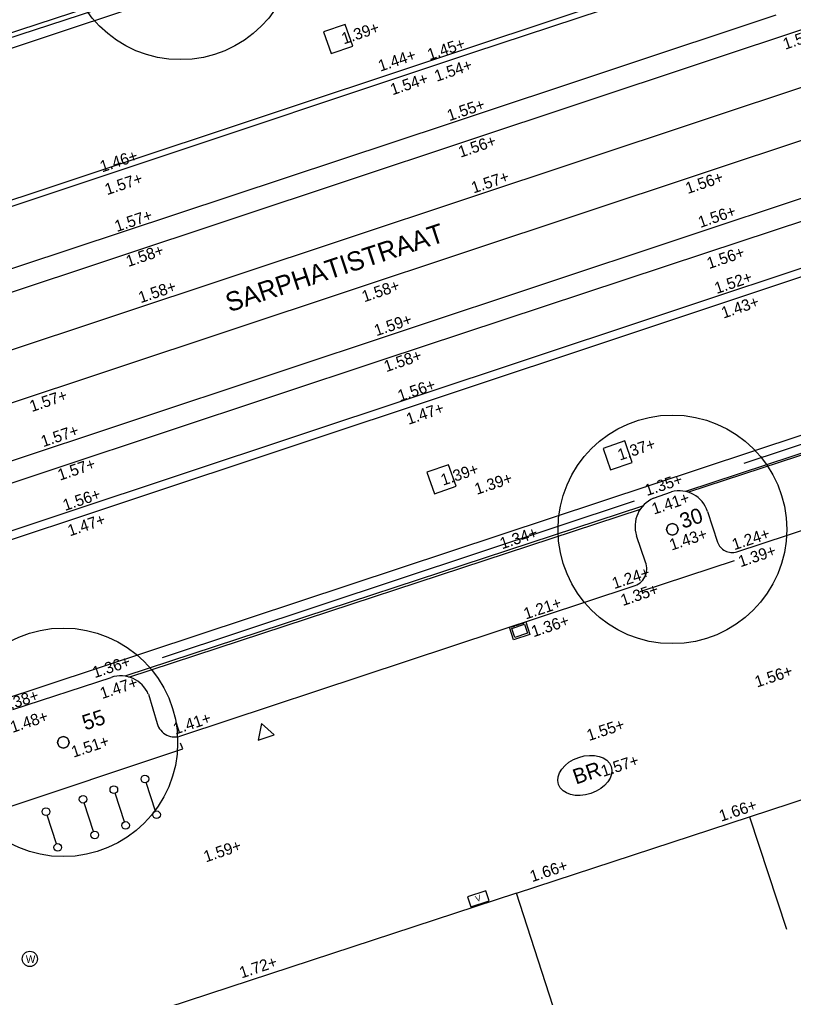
# Model space of a CAD drawing. Extents: x 122462 to 123306, y 485548 to 486417.
# Drawn here: x 122686.41 to 122706.71, y 486120.56 to 486146.23 of the extents above; entities that cross this region are included whole.
import ezdxf

# ---------------------------------------------------------------- set-up
doc = ezdxf.new("R2010")
doc.units = 0
for name, color, linetype in [('B meubilair trammast', 7, 'Continuous'), ('B RWS-band 115-225x250 mm specie', 7, 'Continuous'), ('B-WE-GR-BOOM-S', 7, 'Continuous'), ('B-WE-GR-BOOM_BOOMDIAMETER', 7, 'Continuous'), ('B-WE-IE-MEUBILAIR_WEGMEUBILAIR-S', 7, 'Continuous'), ('B-WE-IE-MEUBILAIR_WEGMEUBILAIR_FIETSNIETJE-S', 7, 'Continuous'), ('B-WE-KL-DATA_TELECOM_KAST-S', 7, 'Continuous'), ('B-WE-OG-HOOGTEPUNT-S', 7, 'Continuous'), ('B-WE-OG-TOPOGRAFIE_RAILS-G', 7, 'Continuous'), ('B-WE-OG-TOPOGRAFIE_STRAATNAAM', 7, 'Continuous'), ('B-WE-OG-TOPOKAART-G', 7, 'Continuous'), ('B-WE-RI-HWA_KOLK-S', 7, 'Continuous'), ('B-WE-RI-HWA_RIOOLPUT-S', 7, 'Continuous'), ('B-WE-VH-KANTOPSLUITING_OPSLUITBAND_100X200-G', 7, 'Continuous'), ('B-WE-VH-KANTOPSLUITING_TROTTOIRBAND_180 200-G', 7, 'Continuous'), ('B-WE-VH-KANTVERHARDING_EIND_VERHARDING-G', 7, 'Continuous'), ('B-WE-VH-MATERIAALGRENS-G', 7, 'Continuous'), ('B-WE-VH-MATERIAALGRENS_ASFALT-G', 7, 'Continuous'), ('B-WE-VW-MARKERING_LANGS_STREEP_11_010-G', 7, 'Continuous'), ('B-WE-VW-MARKERING_LANGS_STREEP_DOORGETROKKEN_010-G', 7, 'Continuous')]:
    doc.layers.add(name, color=color, linetype=linetype)

msp = doc.modelspace()

# ---------------------------------------------------------------- linework, layer by layer
at = {"layer": 'B meubilair trammast'}
msp.add_lwpolyline([(122692.665, 486127.315), (122693.091, 486127.46), (122692.752, 486127.756)], close=True, dxfattribs=at)
at = {"layer": 'B RWS-band 115-225x250 mm specie'}
for points in [[(122669.847, 486135.87), (122698.323, 486145.37), (122705.772, 486147.833)], [(122708.301, 486140.155), (122702.829, 486138.34), (122672.345, 486128.207)]]:
    msp.add_lwpolyline(points, dxfattribs=at)
at = {"layer": 'B-WE-GR-BOOM-S'}
for centre, radius in [((122690.629, 486148.177), 3), ((122703.536, 486132.849), 3), ((122703.536, 486132.849), 0.15), ((122687.555, 486127.259), 3), ((122687.555, 486127.259), 0.15)]:
    msp.add_circle(centre, radius, dxfattribs=at)
for centre, start, end in [((122703.536, 486132.849), 0, 180), ((122703.536, 486132.849), 180, 0), ((122687.555, 486127.259), 0, 180), ((122687.555, 486127.259), 180, 0)]:
    msp.add_arc(centre, 0.15, start, end, dxfattribs=at)
at = {"layer": 'B-WE-IE-MEUBILAIR_WEGMEUBILAIR-S'}
msp.add_circle((122686.676, 486121.575), 0.2, dxfattribs=at)
msp.add_ellipse((122701.24, 486126.39), major_axis=(-0.69, -0.235), ratio=0.685994, dxfattribs=at)
at = {"layer": 'B-WE-IE-MEUBILAIR_WEGMEUBILAIR_FIETSNIETJE-S'}
for p, q in [((122689.971, 486125.454), (122689.727, 486126.202)), ((122689.156, 486125.174), (122688.911, 486125.921)), ((122688.348, 486124.922), (122688.103, 486125.669)), ((122687.376, 486124.596), (122687.132, 486125.344))]:
    msp.add_line(p, q, dxfattribs=at)
for centre in [(122689.695, 486126.297), (122688.88, 486126.016), (122688.072, 486125.764), (122687.1, 486125.439), (122690.003, 486125.359), (122689.187, 486125.079), (122688.379, 486124.827), (122687.408, 486124.501)]:
    msp.add_circle(centre, 0.1, dxfattribs=at)
at = {"layer": 'B-WE-KL-DATA_TELECOM_KAST-S'}
msp.add_lwpolyline([(122698.639, 486123.364), (122698.164, 486123.208), (122698.251, 486122.942), (122698.727, 486123.098)], close=True, dxfattribs=at)
at = {"layer": 'B-WE-OG-TOPOGRAFIE_RAILS-G'}
for p, q in [((122670.505, 486133.859), (122714.919, 486148.627)), ((122670.96, 486132.492), (122715.373, 486147.26)), ((122671.366, 486131.239), (122712.39, 486144.878)), ((122671.82, 486129.872), (122712.845, 486143.511))]:
    msp.add_line(p, q, dxfattribs=at)
at = {"layer": 'B-WE-OG-TOPOKAART-G'}
msp.add_lwpolyline([(122700.399, 486120.349), (122699.445, 486123.3), (122688.673, 486119.763), (122689.048, 486118.623), (122683.871, 486116.922), (122683.497, 486118.062), (122676.455, 486115.749)], dxfattribs=at)
at = {"layer": 'B-WE-RI-HWA_KOLK-S'}
for p, q in [((122699.261, 486130.282), (122699.688, 486130.424)), ((122699.367, 486130.302), (122699.398, 486130.312)), ((122699.403, 486130.329), (122699.404, 486130.325)), ((122699.427, 486130.337), (122699.428, 486130.332)), ((122699.441, 486130.326), (122699.517, 486130.351)), ((122699.522, 486130.369), (122699.523, 486130.364)), ((122699.545, 486130.376), (122699.547, 486130.372)), ((122699.56, 486130.365), (122699.635, 486130.391)), ((122699.64, 486130.408), (122699.642, 486130.403)), ((122699.688, 486130.424), (122699.798, 486130.091)), ((122699.371, 486129.95), (122699.261, 486130.282)), ((122699.308, 486130.298), (122699.31, 486130.293)), ((122699.322, 486130.287), (122699.367, 486130.302)), ((122699.798, 486130.091), (122699.371, 486129.95))]:
    msp.add_line(p, q, dxfattribs=at)
msp.add_lwpolyline([(122699.735, 486130.123), (122699.402, 486130.013), (122699.324, 486130.25), (122699.656, 486130.36)], close=True, dxfattribs=at)
for centre, start, end in [((122699.395, 486130.321), 288.3203, 18.3203), ((122699.438, 486130.336), 198.3203, 288.3203), ((122699.514, 486130.361), 288.3203, 18.3203), ((122699.556, 486130.375), 198.3203, 288.3203), ((122699.632, 486130.4), 288.3203, 18.3203), ((122699.319, 486130.296), 198.3203, 288.3203)]:
    msp.add_arc(centre, 0.01, start, end, dxfattribs=at)
at = {"layer": 'B-WE-RI-HWA_RIOOLPUT-S'}
for points in [[(122694.385, 486145.905), (122694.582, 486145.338), (122695.149, 486145.535), (122694.952, 486146.102)], [(122702.481, 486134.602), (122702.286, 486135.169), (122701.719, 486134.974), (122701.914, 486134.407)], [(122697.861, 486133.98), (122697.663, 486134.546), (122697.097, 486134.348), (122697.295, 486133.782)]]:
    msp.add_lwpolyline(points, close=True, dxfattribs=at)
at = {"layer": 'B-WE-VH-KANTOPSLUITING_OPSLUITBAND_100X200-G'}
msp.add_lwpolyline([(122699.445, 486123.3), (122705.563, 486125.308), (122706.53, 486122.359)], dxfattribs=at)
at = {"layer": 'B-WE-VH-KANTOPSLUITING_TROTTOIRBAND_180 200-G'}
for points in [[(122689.134, 486146.852), (122675.531, 486142.397), (122670.617, 486140.763)], [(122705.227, 486132.261), (122709.32, 486133.608), (122719.352, 486136.936)], [(122703.042, 486133.666), (122703.51, 486133.833)], [(122704.46, 486133.316), (122704.721, 486132.517)], [(122702.834, 486131.988), (122702.598, 486132.678)], [(122690.664, 486127.435), (122702.512, 486131.358)], [(122686.229, 486128.118), (122688.811, 486128.965)], [(122689.786, 486128.522), (122690.018, 486127.754)]]:
    msp.add_lwpolyline(points, dxfattribs=at)
for centre, radius, start, end in [((122703.355, 486132.932), 0.798, 113.0819, 198.5205), ((122703.718, 486133.084), 0.777, 17.3585, 105.5305), ((122705.102, 486132.641), 0.4, 198.1189, 288.2093), ((122702.391, 486131.817), 0.475, 284.7543, 21.1015), ((122689.057, 486128.213), 0.791, 22.9882, 108.1416), ((122690.482, 486127.88), 0.481, 195.2356, 292.2034)]:
    msp.add_arc(centre, radius, start, end, dxfattribs=at)
at = {"layer": 'B-WE-VH-KANTVERHARDING_EIND_VERHARDING-G'}
for points in [[(122702.69, 486131.215), (122705.163, 486132.032)], [(122685.809, 486125.603), (122685.84, 486125.468), (122690.695, 486127.088), (122690.628, 486127.234)]]:
    msp.add_lwpolyline(points, dxfattribs=at)
at = {"layer": 'B-WE-VH-MATERIAALGRENS-G'}
msp.add_lwpolyline([(122705.563, 486125.308), (122708.306, 486126.208)], dxfattribs=at)
at = {"layer": 'B-WE-VH-MATERIAALGRENS_ASFALT-G'}
for points in [[(122689.178, 486146.73), (122682.431, 486144.534), (122673.133, 486141.431), (122670.707, 486140.578), (122670.551, 486140.725)], [(122670.318, 486134.438), (122689.137, 486140.666), (122697.659, 486143.491), (122706.259, 486146.355)], [(122707.935, 486141.266), (122704.407, 486140.099), (122695.913, 486137.294), (122687.388, 486134.451), (122671.994, 486129.333)], [(122709.518, 486135.698), (122703.88, 486133.844)], [(122702.75, 486133.455), (122689.171, 486128.996)]]:
    msp.add_lwpolyline(points, dxfattribs=at)
at = {"layer": 'B-WE-VW-MARKERING_LANGS_STREEP_11_010-G'}
for points in [[(122701.228, 486150.481), (122671.658, 486140.638)], [(122709.603, 486136.203), (122680.508, 486126.571), (122673.652, 486124.285)], [(122709.675, 486135.987), (122705.415, 486134.581)], [(122702.535, 486133.589), (122690.152, 486129.481)]]:
    msp.add_lwpolyline(points, dxfattribs=at)
at = {"layer": 'B-WE-VW-MARKERING_LANGS_STREEP_DOORGETROKKEN_010-G'}
for p, q in [((122718.77, 486138.702), (122703.962, 486133.822)), ((122702.689, 486133.372), (122689.266, 486128.964))]:
    msp.add_line(p, q, dxfattribs=at)
for points in [[(122669.745, 486136.183), (122671.391, 486136.575), (122705.718, 486147.995)], [(122708.366, 486139.96), (122701.962, 486137.822), (122672.4, 486127.989)]]:
    msp.add_lwpolyline(points, dxfattribs=at)

# ---------------------------------------------------------------- texts
at = {"layer": 'B-WE-GR-BOOM_BOOMDIAMETER'}
for s, rotation, p in [('30', 18.2008, (122703.808, 486132.863)), ('55', 18.3203, (122688.129, 486127.569))]:
    msp.add_text(s, height=0.4, rotation=rotation, dxfattribs=at).set_placement(p)
at = {"layer": 'B-WE-IE-MEUBILAIR_WEGMEUBILAIR-S'}
msp.add_text('BR', height=0.4, rotation=18.8313, dxfattribs=at).set_placement((122701.007, 486126.149))
msp.add_text('W', height=0.2, dxfattribs=at).set_placement((122686.57, 486121.47))
at = {"layer": 'B-WE-KL-DATA_TELECOM_KAST-S'}
msp.add_text('V', height=0.16, rotation=18.1777, dxfattribs=at).set_placement((122698.396, 486123.066))
at = {"layer": 'B-WE-OG-HOOGTEPUNT-S'}
for s, rotation, p in [('1.39+', 18.4111, (122694.913, 486145.577)), ('1.54+', 18.5941, (122706.497, 486145.435)), ('1.45+', 18.4111, (122697.165, 486145.157)), ('1.44+', 18.4111, (122695.875, 486144.861)), ('1.54+', 18.5941, (122697.352, 486144.595)), ('1.54+', 18.4111, (122696.192, 486144.24)), ('1.55+', 18.5941, (122697.684, 486143.559)), ('1.56+', 18.5941, (122697.978, 486142.602)), ('1.46+', 18.3037, (122688.572, 486142.217)), ('1.57+', 18.3037, (122688.702, 486141.619)), ('1.57+', 18.5941, (122698.32, 486141.663)), ('1.56+', 18.5941, (122703.94, 486141.649)), ('1.57+', 18.5941, (122688.96, 486140.652)), ('1.56+', 18.5941, (122704.272, 486140.759)), ('1.58+', 18.5941, (122689.259, 486139.733)), ('1.56+', 18.5941, (122704.5, 486139.679)), ('1.52+', 18.5941, (122704.701, 486139.026)), ('1.58+', 18.5941, (122689.584, 486138.782)), ('1.58+', 18.5941, (122695.448, 486138.806)), ('1.43+', 18.5941, (122704.879, 486138.38)), ('1.59+', 18.5941, (122695.77, 486137.916)), ('1.58+', 18.5941, (122696.026, 486136.972)), ('1.56+', 18.5941, (122696.388, 486136.202)), ('1.57+', 18.5941, (122686.728, 486135.926)), ('1.47+', 18.3983, (122696.612, 486135.591)), ('1.57+', 18.5941, (122687.025, 486135.003)), ('1.37+', 18.3203, (122702.158, 486134.651)), ('1.57+', 18.5941, (122687.466, 486134.125)), ('1.39+', 18.3203, (122697.517, 486133.993)), ('1.39+', 18.3203, (122698.404, 486133.753)), ('1.35+', 18.3203, (122702.868, 486133.722)), ('1.56+', 18.5941, (122687.601, 486133.331)), ('1.41+', 18.3203, (122703.052, 486133.234)), ('1.47+', 18.5941, (122687.727, 486132.663)), ('1.34+', 18.3203, (122699.067, 486132.325)), ('1.43+', 18.3203, (122703.517, 486132.29)), ('1.24+', 18.3203, (122705.16, 486132.299)), ('1.39+', 18.3203, (122705.323, 486131.852)), ('1.24+', 18.3203, (122702.011, 486131.278)), ('1.35+', 18.3203, (122702.237, 486130.836)), ('1.21+', 18.3203, (122699.691, 486130.481)), ('1.36+', 18.3203, (122699.893, 486130.015)), ('1.36+', 18.1815, (122688.377, 486128.942)), ('1.56+', 18.2074, (122705.757, 486128.695)), ('1.47+', 18.1815, (122688.574, 486128.393)), ('1.38+', 18.1815, (122685.975, 486128.053)), ('1.48+', 18.1815, (122686.22, 486127.505)), ('1.41+', 18.1815, (122690.495, 486127.46)), ('1.55+', 18.2074, (122701.347, 486127.291)), ('1.51+', 18.1815, (122687.822, 486126.854)), ('1.57+', 18.2074, (122701.721, 486126.349)), ('1.66+', 18.2074, (122704.819, 486125.175)), ('1.59+', 18.6944, (122691.295, 486124.105)), ('1.66+', 18.2074, (122699.855, 486123.588)), ('1.72+', 18.1815, (122692.231, 486121.061))]:
    msp.add_text(s, height=0.3, rotation=rotation, dxfattribs=at).set_placement(p)
at = {"layer": 'B-WE-OG-TOPOGRAFIE_STRAATNAAM'}
msp.add_text('SARPHATISTRAAT', height=0.5, rotation=18.2298, dxfattribs=at).set_placement((122691.911, 486138.544))

doc.saveas('drawing.dxf')
